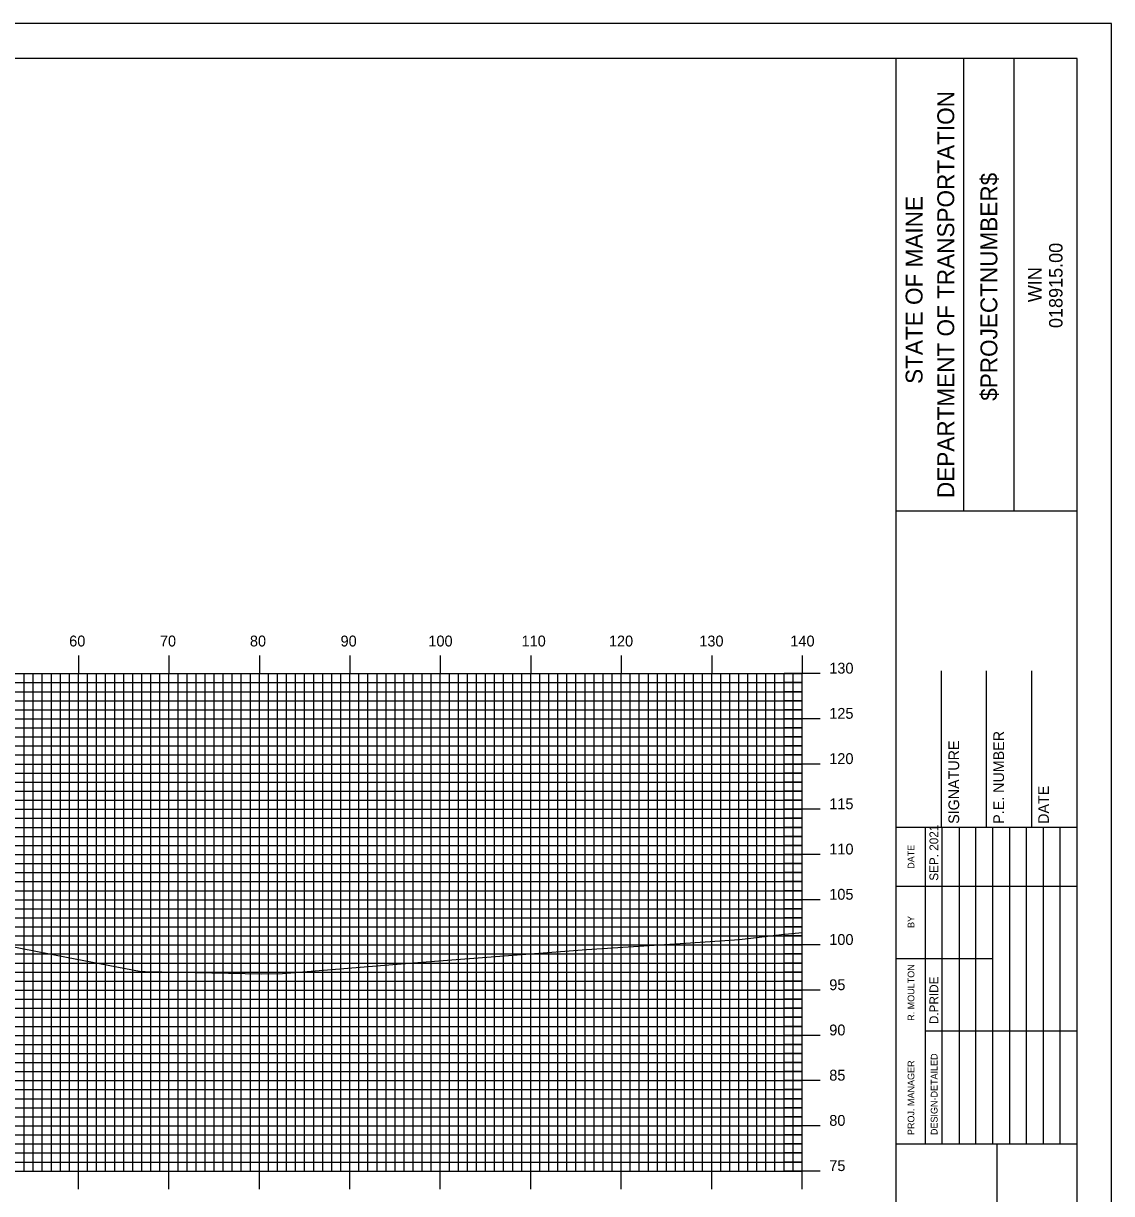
# Model space of a CAD drawing. Extents: x 1684012 to 1684355, y 461260 to 461480.
# Drawn here: x 1684231.6 to 1684351.9, y 461350.6 to 461480 of the extents above; entities that cross this region are included whole.
import ezdxf

# ---------------------------------------------------------------- set-up
doc = ezdxf.new("R2010")
doc.units = 0
for name, color, linetype in [('BORDER', 7, 'Continuous'), ('H_V ANNOTATION', 7, 'Continuous'), ('MAJOR', 7, 'Continuous'), ('MINOR', 7, 'Continuous'), ('PLOT BOUNDARY', 7, 'Continuous'), ('S_Roadway_Centerline', 7, 'Continuous')]:
    doc.layers.add(name, color=color, linetype=linetype)

msp = doc.modelspace()

# ---------------------------------------------------------------- linework, layer by layer
at = {"layer": 'BORDER'}
for p, q in [((1684328.09, 461266.07), (1684328.09, 461476.07)), ((1684335.55, 461426.07), (1684335.55, 461476.07)), ((1684341.14, 461426.07), (1684341.14, 461476.07)), ((1684328.09, 461426.06), (1684348.09, 461426.06)), ((1684333.09, 461391.08), (1684333.09, 461408.37)), ((1684338.09, 461391.08), (1684338.09, 461408.37)), ((1684343.09, 461391.08), (1684343.09, 461408.37)), ((1684328.09, 461391.08), (1684348.09, 461391.08)), ((1684328.09, 461356.08), (1684348.09, 461356.08)), ((1684339.27, 461286.08), (1684339.27, 461356.08))]:
    msp.add_line(p, q, dxfattribs=at)
msp.add_lwpolyline([(1684028.09, 461266.07), (1684348.09, 461266.07), (1684348.09, 461476.07), (1684028.09, 461476.07)], close=True, dxfattribs=at)
for points in [[(1684331.32, 461384.58), (1684331.32, 461391.08)], [(1684333.19, 461356.08), (1684333.19, 461391.08)], [(1684335.05, 461391.08), (1684335.05, 461356.08)], [(1684336.91, 461356.08), (1684336.91, 461391.08)], [(1684338.78, 461356.08), (1684338.78, 461391.08)], [(1684340.64, 461356.08), (1684340.64, 461391.08)], [(1684342.5, 461356.08), (1684342.5, 461391.08)], [(1684344.37, 461356.08), (1684344.37, 461391.08)], [(1684346.23, 461356.08), (1684346.23, 461391.08)], [(1684331.32, 461356.08), (1684331.32, 461389.67)], [(1684328.09, 461384.58), (1684348.09, 461384.58)], [(1684328.09, 461376.58), (1684331.32, 461376.58)], [(1684331.32, 461376.58), (1684338.77, 461376.58)], [(1684331.32, 461368.58), (1684348.09, 461368.58)]]:
    msp.add_lwpolyline(points, dxfattribs=at)
at = {"layer": 'MAJOR'}
for p, q in [((1684237.69, 461410.08), (1684237.69, 461408.07)), ((1684247.69, 461410.08), (1684247.69, 461408.07)), ((1684257.69, 461410.08), (1684257.69, 461408.07)), ((1684267.69, 461410.08), (1684267.69, 461408.07)), ((1684277.69, 461410.08), (1684277.69, 461408.07)), ((1684287.69, 461410.08), (1684287.69, 461408.07)), ((1684297.69, 461410.08), (1684297.69, 461408.07)), ((1684307.69, 461410.08), (1684307.69, 461408.07)), ((1684317.69, 461410.08), (1684317.69, 461408.07)), ((1684037.69, 461408.07), (1684317.69, 461408.07)), ((1684037.69, 461408.07), (1684317.69, 461408.07)), ((1684237.69, 461353.07), (1684237.69, 461408.07)), ((1684247.69, 461353.07), (1684247.69, 461408.07)), ((1684257.69, 461353.07), (1684257.69, 461408.07)), ((1684267.69, 461353.07), (1684267.69, 461408.07)), ((1684277.69, 461353.07), (1684277.69, 461408.07)), ((1684287.69, 461353.07), (1684287.69, 461408.07)), ((1684297.69, 461353.07), (1684297.69, 461408.07)), ((1684307.69, 461353.07), (1684307.69, 461408.07)), ((1684319.69, 461408.07), (1684315.69, 461408.07)), ((1684317.69, 461353.07), (1684317.69, 461408.07)), ((1684317.69, 461353.07), (1684317.69, 461408.07)), ((1684037.69, 461403.07), (1684317.69, 461403.07)), ((1684319.69, 461403.07), (1684315.69, 461403.07)), ((1684037.69, 461398.07), (1684317.69, 461398.07)), ((1684319.69, 461398.07), (1684315.69, 461398.07)), ((1684037.69, 461393.07), (1684317.69, 461393.07)), ((1684319.69, 461393.07), (1684315.69, 461393.07)), ((1684037.69, 461388.07), (1684317.69, 461388.07)), ((1684319.69, 461388.07), (1684315.69, 461388.07)), ((1684037.69, 461383.07), (1684317.69, 461383.07)), ((1684319.69, 461383.07), (1684315.69, 461383.07)), ((1684037.69, 461378.07), (1684317.69, 461378.07)), ((1684319.69, 461378.07), (1684315.69, 461378.07)), ((1684037.69, 461373.07), (1684317.69, 461373.07)), ((1684319.69, 461373.07), (1684315.69, 461373.07)), ((1684037.69, 461368.07), (1684317.69, 461368.07)), ((1684319.69, 461368.07), (1684315.69, 461368.07)), ((1684037.69, 461363.07), (1684317.69, 461363.07)), ((1684319.69, 461363.07), (1684315.69, 461363.07)), ((1684037.69, 461358.07), (1684317.69, 461358.07)), ((1684319.69, 461358.07), (1684315.69, 461358.07)), ((1684037.69, 461353.07), (1684317.69, 461353.07)), ((1684037.69, 461353.07), (1684317.69, 461353.07)), ((1684237.69, 461351.07), (1684237.69, 461353.07)), ((1684247.69, 461351.07), (1684247.69, 461353.07)), ((1684257.69, 461351.07), (1684257.69, 461353.07)), ((1684267.69, 461351.07), (1684267.69, 461353.07)), ((1684277.69, 461351.07), (1684277.69, 461353.07)), ((1684287.69, 461351.07), (1684287.69, 461353.07)), ((1684297.69, 461351.07), (1684297.69, 461353.07)), ((1684307.69, 461351.07), (1684307.69, 461353.07)), ((1684319.69, 461353.07), (1684315.69, 461353.07)), ((1684317.69, 461351.07), (1684317.69, 461353.07))]:
    msp.add_line(p, q, dxfattribs=at)
at = {"layer": 'MINOR'}
for p, q in [((1684231.69, 461353.07), (1684231.69, 461408.07)), ((1684232.69, 461353.07), (1684232.69, 461408.07)), ((1684233.69, 461353.07), (1684233.69, 461408.07)), ((1684234.69, 461353.07), (1684234.69, 461408.07)), ((1684235.69, 461353.07), (1684235.69, 461408.07)), ((1684236.69, 461353.07), (1684236.69, 461408.07)), ((1684238.69, 461353.07), (1684238.69, 461408.07)), ((1684239.69, 461353.07), (1684239.69, 461408.07)), ((1684240.69, 461353.07), (1684240.69, 461408.07)), ((1684241.69, 461353.07), (1684241.69, 461408.07)), ((1684242.69, 461353.07), (1684242.69, 461408.07)), ((1684243.69, 461353.07), (1684243.69, 461408.07)), ((1684244.69, 461353.07), (1684244.69, 461408.07)), ((1684245.69, 461353.07), (1684245.69, 461408.07)), ((1684246.69, 461353.07), (1684246.69, 461408.07)), ((1684248.69, 461353.07), (1684248.69, 461408.07)), ((1684249.69, 461353.07), (1684249.69, 461408.07)), ((1684250.69, 461353.07), (1684250.69, 461408.07)), ((1684251.69, 461353.07), (1684251.69, 461408.07)), ((1684252.69, 461353.07), (1684252.69, 461408.07)), ((1684253.69, 461353.07), (1684253.69, 461408.07)), ((1684254.69, 461353.07), (1684254.69, 461408.07)), ((1684255.69, 461353.07), (1684255.69, 461408.07)), ((1684256.69, 461353.07), (1684256.69, 461408.07)), ((1684258.69, 461353.07), (1684258.69, 461408.07)), ((1684259.69, 461353.07), (1684259.69, 461408.07)), ((1684260.69, 461353.07), (1684260.69, 461408.07)), ((1684261.69, 461353.07), (1684261.69, 461408.07)), ((1684262.69, 461353.07), (1684262.69, 461408.07)), ((1684263.69, 461353.07), (1684263.69, 461408.07)), ((1684264.69, 461353.07), (1684264.69, 461408.07)), ((1684265.69, 461353.07), (1684265.69, 461408.07)), ((1684266.69, 461353.07), (1684266.69, 461408.07)), ((1684268.69, 461353.07), (1684268.69, 461408.07)), ((1684269.69, 461353.07), (1684269.69, 461408.07)), ((1684270.69, 461353.07), (1684270.69, 461408.07)), ((1684271.69, 461353.07), (1684271.69, 461408.07)), ((1684272.69, 461353.07), (1684272.69, 461408.07)), ((1684273.69, 461353.07), (1684273.69, 461408.07)), ((1684274.69, 461353.07), (1684274.69, 461408.07)), ((1684275.69, 461353.07), (1684275.69, 461408.07)), ((1684276.69, 461353.07), (1684276.69, 461408.07)), ((1684278.69, 461353.07), (1684278.69, 461408.07)), ((1684279.69, 461353.07), (1684279.69, 461408.07)), ((1684280.69, 461353.07), (1684280.69, 461408.07)), ((1684281.69, 461353.07), (1684281.69, 461408.07)), ((1684282.69, 461353.07), (1684282.69, 461408.07)), ((1684283.69, 461353.07), (1684283.69, 461408.07)), ((1684284.69, 461353.07), (1684284.69, 461408.07)), ((1684285.69, 461353.07), (1684285.69, 461408.07)), ((1684286.69, 461353.07), (1684286.69, 461408.07)), ((1684288.69, 461353.07), (1684288.69, 461408.07)), ((1684289.69, 461353.07), (1684289.69, 461408.07)), ((1684290.69, 461353.07), (1684290.69, 461408.07)), ((1684291.69, 461353.07), (1684291.69, 461408.07)), ((1684292.69, 461353.07), (1684292.69, 461408.07)), ((1684293.69, 461353.07), (1684293.69, 461408.07)), ((1684294.69, 461353.07), (1684294.69, 461408.07)), ((1684295.69, 461353.07), (1684295.69, 461408.07)), ((1684296.69, 461353.07), (1684296.69, 461408.07)), ((1684298.69, 461353.07), (1684298.69, 461408.07)), ((1684299.69, 461353.07), (1684299.69, 461408.07)), ((1684300.69, 461353.07), (1684300.69, 461408.07)), ((1684301.69, 461353.07), (1684301.69, 461408.07)), ((1684302.69, 461353.07), (1684302.69, 461408.07)), ((1684303.69, 461353.07), (1684303.69, 461408.07)), ((1684304.69, 461353.07), (1684304.69, 461408.07)), ((1684305.69, 461353.07), (1684305.69, 461408.07)), ((1684306.69, 461353.07), (1684306.69, 461408.07)), ((1684308.69, 461353.07), (1684308.69, 461408.07)), ((1684309.69, 461353.07), (1684309.69, 461408.07)), ((1684310.69, 461353.07), (1684310.69, 461408.07)), ((1684311.69, 461353.07), (1684311.69, 461408.07)), ((1684312.69, 461353.07), (1684312.69, 461408.07)), ((1684313.69, 461353.07), (1684313.69, 461408.07)), ((1684314.69, 461353.07), (1684314.69, 461408.07)), ((1684315.69, 461353.07), (1684315.69, 461408.07)), ((1684316.69, 461353.07), (1684316.69, 461408.07)), ((1684037.69, 461407.07), (1684317.69, 461407.07)), ((1684037.69, 461406.07), (1684317.69, 461406.07)), ((1684317.69, 461407.07), (1684315.69, 461407.07)), ((1684317.69, 461406.07), (1684315.69, 461406.07)), ((1684037.69, 461405.07), (1684317.69, 461405.07)), ((1684317.69, 461405.07), (1684315.69, 461405.07)), ((1684037.69, 461404.07), (1684317.69, 461404.07)), ((1684317.69, 461404.07), (1684315.69, 461404.07)), ((1684037.69, 461402.07), (1684317.69, 461402.07)), ((1684037.69, 461401.07), (1684317.69, 461401.07)), ((1684317.69, 461402.07), (1684315.69, 461402.07)), ((1684317.69, 461401.07), (1684315.69, 461401.07)), ((1684037.69, 461400.07), (1684317.69, 461400.07)), ((1684317.69, 461400.07), (1684315.69, 461400.07)), ((1684037.69, 461399.07), (1684317.69, 461399.07)), ((1684317.69, 461399.07), (1684315.69, 461399.07)), ((1684037.69, 461397.07), (1684317.69, 461397.07)), ((1684317.69, 461397.07), (1684315.69, 461397.07)), ((1684037.69, 461396.07), (1684317.69, 461396.07)), ((1684317.69, 461396.07), (1684315.69, 461396.07)), ((1684037.69, 461395.07), (1684317.69, 461395.07)), ((1684317.69, 461395.07), (1684315.69, 461395.07)), ((1684037.69, 461394.07), (1684317.69, 461394.07)), ((1684317.69, 461394.07), (1684315.69, 461394.07)), ((1684037.69, 461392.07), (1684317.69, 461392.07)), ((1684317.69, 461392.07), (1684315.69, 461392.07)), ((1684037.69, 461391.07), (1684317.69, 461391.07)), ((1684317.69, 461391.07), (1684315.69, 461391.07)), ((1684037.69, 461390.07), (1684317.69, 461390.07)), ((1684317.69, 461390.07), (1684315.69, 461390.07)), ((1684037.69, 461389.07), (1684317.69, 461389.07)), ((1684317.69, 461389.07), (1684315.69, 461389.07)), ((1684037.69, 461387.07), (1684317.69, 461387.07)), ((1684317.69, 461387.07), (1684315.69, 461387.07)), ((1684037.69, 461386.07), (1684317.69, 461386.07)), ((1684317.69, 461386.07), (1684315.69, 461386.07)), ((1684037.69, 461385.07), (1684317.69, 461385.07)), ((1684317.69, 461385.07), (1684315.69, 461385.07)), ((1684037.69, 461384.07), (1684317.69, 461384.07)), ((1684317.69, 461384.07), (1684315.69, 461384.07)), ((1684037.69, 461382.07), (1684317.69, 461382.07)), ((1684317.69, 461382.07), (1684315.69, 461382.07)), ((1684037.69, 461381.07), (1684317.69, 461381.07)), ((1684317.69, 461381.07), (1684315.69, 461381.07)), ((1684037.69, 461380.07), (1684317.69, 461380.07)), ((1684037.69, 461379.07), (1684317.69, 461379.07)), ((1684317.69, 461380.07), (1684315.69, 461380.07)), ((1684317.69, 461379.07), (1684315.69, 461379.07)), ((1684037.69, 461377.07), (1684317.69, 461377.07)), ((1684317.69, 461377.07), (1684315.69, 461377.07)), ((1684037.69, 461376.07), (1684317.69, 461376.07)), ((1684037.69, 461375.07), (1684317.69, 461375.07)), ((1684317.69, 461376.07), (1684315.69, 461376.07)), ((1684317.69, 461375.07), (1684315.69, 461375.07)), ((1684037.69, 461374.07), (1684317.69, 461374.07)), ((1684317.69, 461374.07), (1684315.69, 461374.07)), ((1684037.69, 461372.07), (1684317.69, 461372.07)), ((1684317.69, 461372.07), (1684315.69, 461372.07)), ((1684037.69, 461371.07), (1684317.69, 461371.07)), ((1684037.69, 461370.07), (1684317.69, 461370.07)), ((1684317.69, 461371.07), (1684315.69, 461371.07)), ((1684317.69, 461370.07), (1684315.69, 461370.07)), ((1684037.69, 461369.07), (1684317.69, 461369.07)), ((1684317.69, 461369.07), (1684315.69, 461369.07)), ((1684037.69, 461367.07), (1684317.69, 461367.07)), ((1684037.69, 461366.07), (1684317.69, 461366.07)), ((1684317.69, 461367.07), (1684315.69, 461367.07)), ((1684317.69, 461366.07), (1684315.69, 461366.07)), ((1684037.69, 461365.07), (1684317.69, 461365.07)), ((1684317.69, 461365.07), (1684315.69, 461365.07)), ((1684037.69, 461364.07), (1684317.69, 461364.07)), ((1684317.69, 461364.07), (1684315.69, 461364.07)), ((1684037.69, 461362.07), (1684317.69, 461362.07)), ((1684037.69, 461361.07), (1684317.69, 461361.07)), ((1684317.69, 461362.07), (1684315.69, 461362.07)), ((1684317.69, 461361.07), (1684315.69, 461361.07)), ((1684037.69, 461360.07), (1684317.69, 461360.07)), ((1684317.69, 461360.07), (1684315.69, 461360.07)), ((1684037.69, 461359.07), (1684317.69, 461359.07)), ((1684317.69, 461359.07), (1684315.69, 461359.07)), ((1684037.69, 461357.07), (1684317.69, 461357.07)), ((1684317.69, 461357.07), (1684315.69, 461357.07)), ((1684037.69, 461356.07), (1684317.69, 461356.07)), ((1684317.69, 461356.07), (1684315.69, 461356.07)), ((1684037.69, 461355.07), (1684317.69, 461355.07)), ((1684317.69, 461355.07), (1684315.69, 461355.07)), ((1684037.69, 461354.07), (1684317.69, 461354.07)), ((1684317.69, 461354.07), (1684315.69, 461354.07))]:
    msp.add_line(p, q, dxfattribs=at)
at = {"layer": 'PLOT BOUNDARY'}
msp.add_lwpolyline([(1684011.9, 461259.95), (1684351.9, 461259.95), (1684351.9, 461479.95), (1684011.9, 461479.95)], close=True, dxfattribs=at)
at = {"layer": 'S_Roadway_Centerline'}
msp.add_lwpolyline([(1684229.58, 461378.06), (1684236.38, 461376.72), (1684244.6, 461375.14), (1684245.07, 461375.13), (1684257.96, 461374.88), (1684260.23, 461374.92), (1684272.45, 461375.91), (1684277.51, 461376.33), (1684283.78, 461376.81), (1684293.84, 461377.57), (1684304.78, 461378.27), (1684310.75, 461378.69), (1684315.42, 461379.24), (1684317.69, 461379.46)], dxfattribs=at)

# ---------------------------------------------------------------- texts
at = {"layer": 'BORDER'}
for s, height, p in [('DEPARTMENT OF TRANSPORTATION', 1.8635, (1684334.5, 461427.48)), ('$PROJECTNUMBER$', 1.8635, (1684339.27, 461438.23)), ('STATE OF MAINE', 1.8635, (1684331, 461440.1)), ('018915.00', 1.491, (1684346.48, 461446.27)), ('WIN', 1.491, (1684344.16, 461449.13)), ('P.E. NUMBER', 1.1811, (1684340.01, 461391.46)), ('SIGNATURE', 1.181, (1684335.05, 461391.46)), ('DATE', 1.181, (1684344.97, 461391.46)), ('SEP. 2021', 0.969, (1684332.74, 461385.17)), ('DATE', 0.743, (1684330.1, 461386.49)), ('BY', 0.743, (1684330.1, 461379.95)), ('R. MOULTON', 0.745, (1684330.1, 461369.68)), ('D.PRIDE', 0.969, (1684332.74, 461369.32)), ('DESIGN-DETAILED', 0.7455, (1684332.66, 461357.05)), ('PROJ. MANAGER', 0.7455, (1684330.1, 461357.05))]:
    msp.add_text(s, height=height, rotation=90, dxfattribs=at).set_placement(p)
at = {"layer": 'H_V ANNOTATION'}
for s, p in [('60', (1684236.66, 461411.07)), ('70', (1684246.69, 461411.07)), ('80', (1684256.64, 461411.07)), ('90', (1684266.66, 461411.07)), ('100', (1684276.37, 461411.07)), ('110', (1684286.67, 461411.07)), ('120', (1684296.33, 461411.07)), ('130', (1684306.32, 461411.07)), ('140', (1684316.39, 461411.07)), ('130', (1684320.69, 461408.07)), ('125', (1684320.69, 461403.07)), ('120', (1684320.69, 461398.07)), ('115', (1684320.69, 461393.07)), ('110', (1684320.69, 461388.07)), ('105', (1684320.69, 461383.07)), ('100', (1684320.69, 461378.07)), ('95', (1684320.69, 461373.07)), ('90', (1684320.69, 461368.07)), ('85', (1684320.69, 461363.07)), ('80', (1684320.69, 461358.07)), ('75', (1684320.69, 461353.07))]:
    msp.add_text(s, height=1.2, dxfattribs=at).set_placement(p)

doc.saveas('drawing.dxf')
